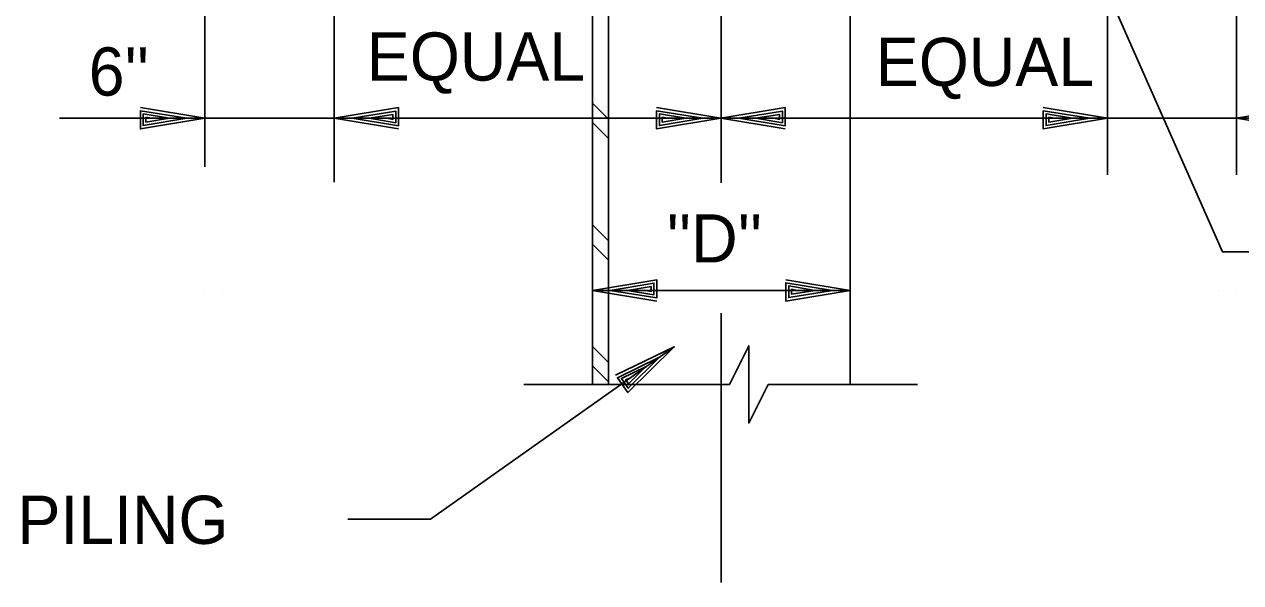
# Model space of a CAD drawing. Extents: x 22411.4 to 22495.4, y 22369.6 to 22415.
# Drawn here: x 22414.588 to 22419.306, y 22387.777 to 22389.941 of the extents above; entities that cross this region are included whole.
import ezdxf

# ---------------------------------------------------------------- set-up
doc = ezdxf.new("R2010")
doc.units = 0
for name, color, linetype in [('Level 1', 7, 'Continuous'), ('Level 2', 7, 'Continuous'), ('Level 4', 7, 'Continuous'), ('Level 8', 7, 'Continuous')]:
    doc.layers.add(name, color=color, linetype=linetype)

msp = doc.modelspace()

# ---------------------------------------------------------------- linework, layer by layer
at = {"layer": 'Level 1'}
for p, q in [((22417.2912, 22389.3264), (22417.2912, 22398.4141)), ((22415.2872, 22392.1809), (22415.2872, 22389.3882)), ((22419.2894, 22392.1948), (22419.2894, 22389.3573)), ((22415.7894, 22391.5095), (22415.7894, 22389.3288)), ((22418.7894, 22391.4528), (22418.7894, 22389.3573)), ((22414.7247, 22389.5767), (22415.2872, 22389.5767)), ((22415.2872, 22389.5767), (22415.7894, 22389.5767)), ((22415.7894, 22389.5767), (22417.2894, 22389.5767)), ((22417.2201, 22389.5767), (22417.2201, 22389.5767)), ((22417.2894, 22389.5767), (22417.2894, 22389.5767)), ((22417.2894, 22389.5767), (22417.2894, 22389.5767)), ((22418.7894, 22389.5767), (22417.2894, 22389.5767)), ((22417.3588, 22389.5767), (22417.3588, 22389.5767)), ((22418.7201, 22389.5767), (22418.7201, 22389.5767)), ((22418.7894, 22389.5767), (22418.7894, 22389.5767)), ((22419.2894, 22389.5767), (22418.7894, 22389.5767)), ((22419.9341, 22389.5767), (22419.2894, 22389.5767)), ((22415.2872, 22388.91), (22415.2872, 22388.91)), ((22415.3565, 22388.91), (22415.3565, 22388.91)), ((22417.7912, 22388.91), (22416.7912, 22388.91)), ((22417.2201, 22388.91), (22417.2201, 22388.91)), ((22417.2894, 22388.91), (22417.2894, 22388.91)), ((22417.2894, 22388.91), (22417.2894, 22388.91)), ((22417.3588, 22388.91), (22417.3588, 22388.91)), ((22419.2201, 22388.91), (22419.2201, 22388.91)), ((22419.2201, 22388.91), (22419.2201, 22388.91)), ((22419.2894, 22388.91), (22419.2894, 22388.91)), ((22419.2894, 22388.91), (22419.2894, 22388.91)), ((22417.2912, 22387.7774), (22417.2912, 22388.8217)), ((22417.1086, 22388.6916), (22417.1086, 22388.6916)), ((22417.052, 22388.6516), (22417.052, 22388.6516)), ((22416.5252, 22388.5454), (22417.3232, 22388.5454)), ((22417.4727, 22388.5454), (22418.0524, 22388.5454))]:
    msp.add_line(p, q, dxfattribs=at)
msp.add_lwpolyline([(22417.3232, 22388.5454), (22417.3977, 22388.6954), (22417.3977, 22388.3958), (22417.4727, 22388.5454)], dxfattribs=at)
at = {"layer": 'Level 2'}
for p, q in [((22416.7912, 22388.5454), (22416.7912, 22391.7183)), ((22416.8537, 22388.5454), (22416.8537, 22391.7183)), ((22417.7912, 22388.5454), (22417.7912, 22390.4475))]:
    msp.add_line(p, q, dxfattribs=at)
for points in [[(22419.4806, 22389.0593), (22419.2355, 22389.0593), (22418.0589, 22391.7183)], [(22415.0379, 22389.618), (22415.2872, 22389.5767), (22415.0379, 22389.5353), (22415.0379, 22389.606), (22415.2179, 22389.5767), (22415.0485, 22389.5487), (22415.0485, 22389.594), (22415.1512, 22389.5767), (22415.0592, 22389.562), (22415.0592, 22389.5807), (22415.0819, 22389.5767)], [(22416.0388, 22389.5353), (22415.7894, 22389.5767), (22416.0388, 22389.618), (22416.0388, 22389.5473), (22415.8588, 22389.5767), (22416.0281, 22389.6047), (22416.0281, 22389.5593), (22415.9254, 22389.5767), (22416.0174, 22389.5913), (22416.0174, 22389.5727), (22415.9948, 22389.5767)], [(22417.0401, 22389.618), (22417.2894, 22389.5767), (22417.0401, 22389.5353), (22417.0401, 22389.606), (22417.2201, 22389.5767), (22417.0508, 22389.5487), (22417.0508, 22389.594), (22417.1534, 22389.5767), (22417.0614, 22389.562), (22417.0614, 22389.5807), (22417.0841, 22389.5767)], [(22417.5388, 22389.5353), (22417.2894, 22389.5767), (22417.5388, 22389.618), (22417.5388, 22389.5473), (22417.3588, 22389.5767), (22417.5281, 22389.6047), (22417.5281, 22389.5593), (22417.4254, 22389.5767), (22417.5174, 22389.5913), (22417.5174, 22389.5727), (22417.4948, 22389.5767)], [(22418.5401, 22389.618), (22418.7894, 22389.5767), (22418.5401, 22389.5353), (22418.5401, 22389.606), (22418.7201, 22389.5767), (22418.5508, 22389.5487), (22418.5508, 22389.594), (22418.6534, 22389.5767), (22418.5614, 22389.562), (22418.5614, 22389.5807), (22418.5841, 22389.5767)], [(22419.5388, 22389.5353), (22419.2894, 22389.5767), (22419.5388, 22389.618), (22419.5388, 22389.5473), (22419.3588, 22389.5767), (22419.5281, 22389.6047), (22419.5281, 22389.5593), (22419.4254, 22389.5767), (22419.5174, 22389.5913), (22419.5174, 22389.5727), (22419.4948, 22389.5767)], [(22417.0405, 22388.8687), (22416.7912, 22388.91), (22417.0405, 22388.9513), (22417.0405, 22388.8807), (22416.8605, 22388.91), (22417.0298, 22388.938), (22417.0298, 22388.8927), (22416.9272, 22388.91), (22417.0192, 22388.9247), (22417.0192, 22388.906), (22416.9965, 22388.91)], [(22417.5418, 22388.9513), (22417.7912, 22388.91), (22417.5418, 22388.8687), (22417.5418, 22388.9393), (22417.7218, 22388.91), (22417.5525, 22388.882), (22417.5525, 22388.9273), (22417.6552, 22388.91), (22417.5632, 22388.8953), (22417.5632, 22388.914), (22417.5858, 22388.91)], [(22415.8431, 22388.023), (22416.1636, 22388.023), (22417.1086, 22388.6916)], [(22416.8812, 22388.5813), (22417.1086, 22388.6916), (22416.9289, 22388.5139), (22416.8881, 22388.5715), (22417.052, 22388.6516), (22416.9299, 22388.5309), (22416.9037, 22388.5679), (22416.9976, 22388.6131), (22416.9309, 22388.5479), (22416.9202, 22388.5632), (22416.941, 22388.573)]]:
    msp.add_lwpolyline(points, dxfattribs=at)
at = {"layer": 'Level 8'}
for p, q in [((22415.2179, 22389.5767), (22415.2179, 22389.5767)), ((22415.2872, 22389.5767), (22415.2872, 22389.5767)), ((22415.7894, 22389.5767), (22415.7894, 22389.5767)), ((22415.8588, 22389.5767), (22415.8588, 22389.5767)), ((22417.2201, 22389.5767), (22417.2201, 22389.5767)), ((22417.2894, 22389.5767), (22417.2894, 22389.5767)), ((22417.2894, 22389.5767), (22417.2894, 22389.5767)), ((22417.3588, 22389.5767), (22417.3588, 22389.5767)), ((22418.7201, 22389.5767), (22418.7201, 22389.5767)), ((22418.7894, 22389.5767), (22418.7894, 22389.5767)), ((22419.2894, 22389.5767), (22419.2894, 22389.5767)), ((22416.7912, 22388.91), (22416.7912, 22388.91)), ((22416.8605, 22388.91), (22416.8605, 22388.91)), ((22417.7218, 22388.91), (22417.7218, 22388.91)), ((22417.7912, 22388.91), (22417.7912, 22388.91))]:
    msp.add_line(p, q, dxfattribs=at)
for points in [[(22416.8537, 22389.5734), (22416.7912, 22389.6359)], [(22416.8537, 22389.4979), (22416.7912, 22389.5604)], [(22416.8537, 22389.102), (22416.7912, 22389.1645)], [(22416.8537, 22389.0265), (22416.7912, 22389.089)], [(22416.8537, 22388.6306), (22416.7912, 22388.6931)], [(22416.8537, 22388.5551), (22416.7912, 22388.6176)]]:
    msp.add_lwpolyline(points, dxfattribs=at)

# ---------------------------------------------------------------- texts
at = {"layer": 'Level 4'}
for s, height, p in [('EQUAL', 0.18667, (22415.9164, 22389.7228)), ('EQUAL', 0.18667, (22417.8907, 22389.702)), ("6''", 0.18667, (22414.8375, 22389.6648)), ("''D''", 0.18667, (22417.079, 22389.0181)), ('STEEL SHEET PILING', 0.186667, (22412.7996, 22387.9276))]:
    msp.add_text(s, height=height, dxfattribs=at).set_placement(p)

doc.saveas('drawing.dxf')
